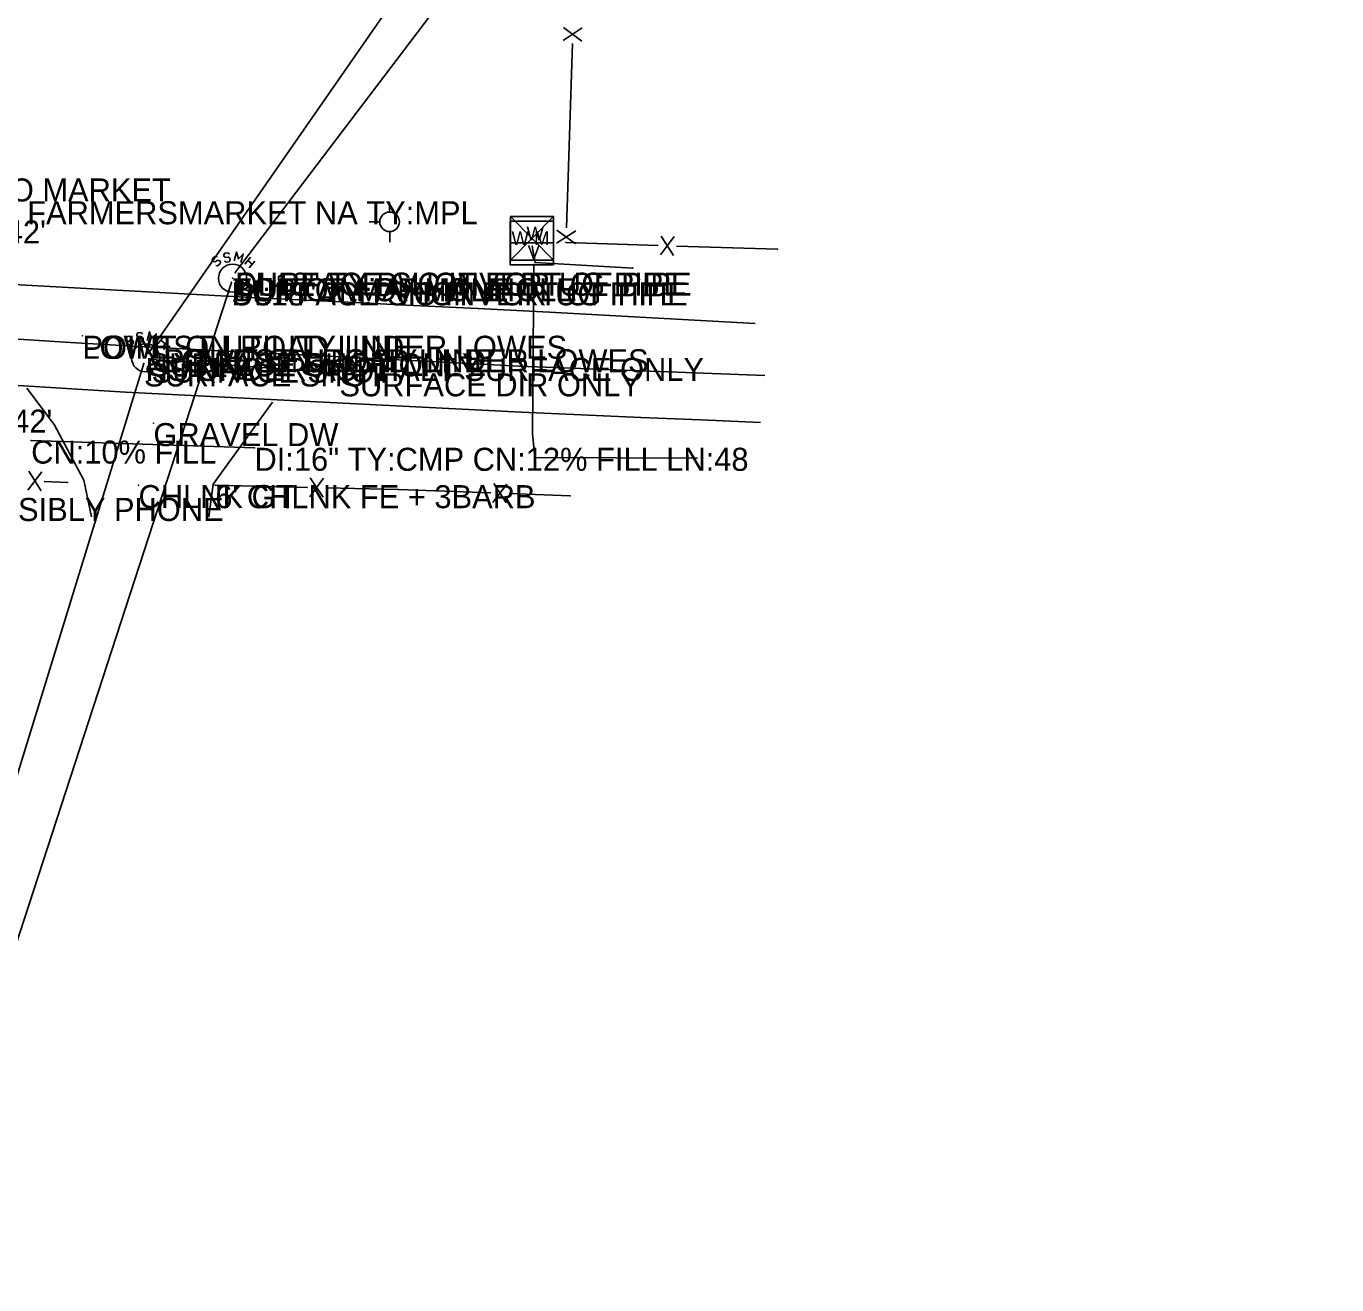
# Model space of a CAD drawing. Extents: x 929765 to 934279, y 1533086 to 1541189.
# Drawn here: x 932210.9 to 932495.1, y 1537318.7 to 1537591.7 of the extents above; entities that cross this region are included whole.
import ezdxf

# ---------------------------------------------------------------- set-up
doc = ezdxf.new("R2010")
doc.units = 0
for name, color, linetype in [('S_CROSS_DRAIN', 7, 'Continuous'), ('S_CROSS_DRAIN_ANNOT', 7, 'Continuous'), ('S_DRG_PT_SYM', 7, 'Continuous'), ('S_DRIVEWAY', 7, 'Continuous'), ('S_EDGE_PAVEMENT', 7, 'Continuous'), ('S_ELECTRIC_UTILITIES_ANNOT', 7, 'Continuous'), ('S_FENCE', 7, 'Continuous'), ('S_FENCE_ANNOT', 7, 'Continuous'), ('S_MANHOLE_ANNOT', 7, 'Continuous'), ('S_MSC_PT_SYM', 7, 'Continuous'), ('S_PAVEMENT_CROWN', 7, 'Continuous'), ('S_SANITARY_SEWER', 7, 'Continuous'), ('S_SANITARY_SEWER_ANNOT', 7, 'Continuous'), ('S_SIGN_ANNOT', 7, 'Continuous'), ('S_SURVEY_TEXT_ANNOT', 7, 'Continuous'), ('S_UNDERGROUND_CABLE_ANNOT', 7, 'Continuous'), ('S_UTILITY_POLE', 7, 'Continuous'), ('S_UTL_PT_SYM', 7, 'Continuous'), ('S_WATER_UTILITIES', 7, 'Continuous')]:
    doc.layers.add(name, color=color, linetype=linetype)

msp = doc.modelspace()

# ---------------------------------------------------------------- linework, layer by layer
at = {"layer": 'S_CROSS_DRAIN'}
msp.add_line((932260.38, 1537500.24), (932211.95, 1537501.81), dxfattribs=at)
at = {"layer": 'S_DRG_PT_SYM'}
for points in [[(932211.95, 1537501.81), (932211.95, 1537501.86), (932211.95, 1537501.81), (932211.9, 1537501.81), (932211.95, 1537501.81), (932211.95, 1537501.76), (932211.95, 1537501.81), (932212, 1537501.81)], [(932260.38, 1537500.24), (932260.38, 1537500.29), (932260.38, 1537500.24), (932260.33, 1537500.24), (932260.38, 1537500.24), (932260.38, 1537500.19), (932260.38, 1537500.24), (932260.43, 1537500.24)]]:
    msp.add_lwpolyline(points, dxfattribs=at)
at = {"layer": 'S_DRIVEWAY'}
for points in [[(932225.03, 1537485.24), (932223.34, 1537493.18), (932216.93, 1537505.32), (932210.97, 1537513.16)], [(932264.28, 1537510.16), (932251.42, 1537492.35), (932250.46, 1537485.26)]]:
    msp.add_lwpolyline(points, dxfattribs=at)
at = {"layer": 'S_EDGE_PAVEMENT'}
for points in [[(932368.97, 1537527.2), (932346.67, 1537528.43), (932324.37, 1537529.66), (932308.86, 1537530.43), (932293.35, 1537531.2), (932277.84, 1537531.96), (932262.32, 1537532.73), (932247.78, 1537533.51), (932233.23, 1537534.29), (932218.68, 1537535.07), (932204.14, 1537535.85), (932182.78, 1537536.97)], [(932061.04, 1537519.67), (932075.98, 1537519.33), (932090.91, 1537518.99), (932105.85, 1537518.66), (932120.78, 1537518.32), (932134.72, 1537517.68), (932148.65, 1537517.03), (932162.59, 1537516.39), (932176.52, 1537515.74), (932190.49, 1537514.88), (932204.46, 1537514.03), (932218.44, 1537513.17), (932232.41, 1537512.32), (932253.88, 1537511.23), (932275.34, 1537510.15), (932296.81, 1537509.07), (932318.28, 1537507.98), (932331.24, 1537507.41), (932344.21, 1537506.84), (932357.18, 1537506.27), (932370.14, 1537505.7)]]:
    msp.add_lwpolyline(points, dxfattribs=at)
at = {"layer": 'S_FENCE'}
for p, q in [((932331.49, 1537591.32), (932327.3, 1537588.58)), ((932331.49, 1537591.32), (932327.3, 1537588.58)), ((932327.4, 1537591.45), (932331.4, 1537588.45)), ((932327.4, 1537591.45), (932331.4, 1537588.45)), ((932330.08, 1537547.34), (932325.9, 1537544.61)), ((932330.08, 1537547.34), (932325.9, 1537544.61)), ((932325.99, 1537547.47), (932329.99, 1537544.48)), ((932325.99, 1537547.47), (932329.99, 1537544.48)), ((932348.43, 1537542.07), (932351.42, 1537546.08)), ((932348.43, 1537542.07), (932351.42, 1537546.08)), ((932348.56, 1537546.17), (932351.29, 1537541.98)), ((932348.56, 1537546.17), (932351.29, 1537541.98)), ((932211.24, 1537491.04), (932214.29, 1537495)), ((932211.24, 1537491.04), (932214.29, 1537495)), ((932211.43, 1537495.13), (932214.1, 1537490.91)), ((932211.43, 1537495.13), (932214.1, 1537490.91)), ((932272.38, 1537489.59), (932275.35, 1537493.62)), ((932272.38, 1537489.59), (932275.35, 1537493.62)), ((932272.48, 1537493.69), (932275.25, 1537489.52)), ((932272.48, 1537493.69), (932275.25, 1537489.52)), ((932312.11, 1537488.37), (932315.13, 1537492.36)), ((932312.11, 1537488.37), (932315.13, 1537492.36)), ((932312.26, 1537492.46), (932314.97, 1537488.26)), ((932312.26, 1537492.46), (932314.97, 1537488.26))]:
    msp.add_line(p, q, dxfattribs=at)
for points in [[(932329.33, 1537587.95), (932328.05, 1537547.97)], [(932329.33, 1537587.95), (932328.05, 1537547.97)], [(932327.95, 1537544.78), (932347.93, 1537544.14)], [(932327.95, 1537544.78), (932347.93, 1537544.14)], [(932351.92, 1537544.01), (932373.82, 1537543.31)], [(932351.92, 1537544.01), (932373.82, 1537543.31)], [(932214.76, 1537492.93), (932219.83, 1537492.69)], [(932214.76, 1537492.93), (932219.83, 1537492.69)], [(932251.87, 1537492.13), (932271.86, 1537491.65)], [(932251.87, 1537492.13), (932271.86, 1537491.65)], [(932275.86, 1537491.56), (932291.63, 1537491.18)], [(932275.86, 1537491.56), (932291.63, 1537491.18)], [(932291.63, 1537491.18), (932311.62, 1537490.44)], [(932291.63, 1537491.18), (932311.62, 1537490.44)], [(932315.61, 1537490.29), (932328.84, 1537489.8)], [(932315.61, 1537490.29), (932328.84, 1537489.8)]]:
    msp.add_lwpolyline(points, dxfattribs=at)
at = {"layer": 'S_MSC_PT_SYM'}
for points in [[(932327.95, 1537544.78), (932327.95, 1537544.83), (932327.95, 1537544.78), (932327.9, 1537544.78), (932327.95, 1537544.78), (932327.95, 1537544.73), (932327.95, 1537544.78), (932328, 1537544.78)], [(932373.82, 1537543.31), (932373.82, 1537543.36), (932373.82, 1537543.31), (932373.77, 1537543.31), (932373.82, 1537543.31), (932373.82, 1537543.26), (932373.82, 1537543.31), (932373.87, 1537543.31)], [(932256.2, 1537538.23), (932256.2, 1537538.28), (932256.2, 1537538.23), (932256.15, 1537538.23), (932256.2, 1537538.23), (932256.2, 1537538.18), (932256.2, 1537538.23), (932256.25, 1537538.23)], [(932255.38, 1537536.13), (932255.38, 1537536.18), (932255.38, 1537536.13), (932255.33, 1537536.13), (932255.38, 1537536.13), (932255.38, 1537536.08), (932255.38, 1537536.13), (932255.43, 1537536.13)], [(932223.06, 1537524.54), (932223.06, 1537524.59), (932223.06, 1537524.54), (932223.01, 1537524.54), (932223.06, 1537524.54), (932223.06, 1537524.49), (932223.06, 1537524.54), (932223.11, 1537524.54)], [(932240.74, 1537521.62), (932240.74, 1537521.67), (932240.74, 1537521.62), (932240.69, 1537521.62), (932240.74, 1537521.62), (932240.74, 1537521.57), (932240.74, 1537521.62), (932240.79, 1537521.62)], [(932238.46, 1537505.59), (932238.46, 1537505.65), (932238.46, 1537505.59), (932238.41, 1537505.59), (932238.46, 1537505.59), (932238.46, 1537505.54), (932238.46, 1537505.59), (932238.51, 1537505.59)], [(932219.83, 1537492.69), (932219.83, 1537492.74), (932219.83, 1537492.69), (932219.78, 1537492.69), (932219.83, 1537492.69), (932219.83, 1537492.64), (932219.83, 1537492.69), (932219.88, 1537492.69)], [(932235.23, 1537492.15), (932235.23, 1537492.2), (932235.23, 1537492.15), (932235.18, 1537492.15), (932235.23, 1537492.15), (932235.23, 1537492.1), (932235.23, 1537492.15), (932235.28, 1537492.15)], [(932251.87, 1537492.13), (932251.87, 1537492.18), (932251.87, 1537492.13), (932251.82, 1537492.13), (932251.87, 1537492.13), (932251.87, 1537492.08), (932251.87, 1537492.13), (932251.92, 1537492.13)], [(932291.63, 1537491.18), (932291.63, 1537491.23), (932291.63, 1537491.18), (932291.58, 1537491.18), (932291.63, 1537491.18), (932291.63, 1537491.13), (932291.63, 1537491.18), (932291.68, 1537491.18)], [(932328.84, 1537489.8), (932328.84, 1537489.85), (932328.84, 1537489.8), (932328.79, 1537489.8), (932328.84, 1537489.8), (932328.84, 1537489.75), (932328.84, 1537489.8), (932328.89, 1537489.8)]]:
    msp.add_lwpolyline(points, dxfattribs=at)
at = {"layer": 'S_PAVEMENT_CROWN'}
msp.add_lwpolyline([(932063.43, 1537531.97), (932077.89, 1537531.23), (932092.36, 1537530.49), (932106.82, 1537529.75), (932121.29, 1537529.01), (932135.07, 1537528.19), (932148.84, 1537527.38), (932162.62, 1537526.56), (932176.4, 1537525.75), (932191.1, 1537524.87), (932205.8, 1537523.99), (932220.5, 1537523.11), (932235.2, 1537522.24), (932255.86, 1537521.16), (932276.51, 1537520.09), (932297.17, 1537519.01), (932317.82, 1537517.94), (932331.13, 1537517.43), (932344.43, 1537516.92), (932357.74, 1537516.42), (932371.04, 1537515.91)], dxfattribs=at)
at = {"layer": 'S_SANITARY_SEWER'}
for p, q in [((932495.13, 1537853.38), (932256.2, 1537538.23)), ((932461.19, 1537843), (932237.41, 1537520.73)), ((932251.3, 1537541.33), (932251.22, 1537540.94)), ((932251.22, 1537540.94), (932251.42, 1537540.67)), ((932251.84, 1537541.72), (932251.3, 1537541.33)), ((932251.42, 1537540.67), (932251.84, 1537540.56)), ((932252.27, 1537541.64), (932251.84, 1537541.72)), ((932251.84, 1537540.56), (932252.39, 1537540.91)), ((932252.39, 1537539.74), (932252, 1537539.82)), ((932252.39, 1537540.91), (932252.85, 1537540.83)), ((932252.93, 1537540.13), (932252.39, 1537539.74)), ((932252.85, 1537540.83), (932253.01, 1537540.56)), ((932253.01, 1537540.56), (932252.93, 1537540.13)), ((932258.28, 1537540.09), (932259.52, 1537541.56)), ((932258.94, 1537540.87), (932259.9, 1537540.05)), ((932260.49, 1537540.75), (932259.25, 1537539.28)), ((932255.38, 1537536.13), (932170.26, 1537274.65)), ((932232.44, 1537524.05), (932232.36, 1537523.66)), ((932232.36, 1537523.66), (932232.55, 1537523.39)), ((932232.98, 1537524.44), (932232.44, 1537524.05)), ((932232.55, 1537523.39), (932232.98, 1537523.27)), ((932233.41, 1537524.36), (932232.98, 1537524.44)), ((932232.98, 1537523.27), (932233.52, 1537523.62)), ((932233.52, 1537522.46), (932233.14, 1537522.54)), ((932233.52, 1537523.62), (932233.99, 1537523.54)), ((932234.07, 1537522.85), (932233.52, 1537522.46)), ((932233.99, 1537523.54), (932234.14, 1537523.27)), ((932234.14, 1537523.27), (932234.07, 1537522.85)), ((932239.41, 1537522.81), (932240.65, 1537524.28)), ((932240.07, 1537523.58), (932241.04, 1537522.77)), ((932241.62, 1537523.47), (932240.38, 1537521.99)), ((932236.41, 1537518.54), (932154.58, 1537252.96)), ((932238.06, 1537519.37), (932278.81, 1537516.4))]:
    msp.add_line(p, q, dxfattribs=at)
for points in [[(932254.94, 1537542.26), (932254.6, 1537542.53), (932253.94, 1537542.46), (932253.7, 1537542.11), (932253.74, 1537541.8), (932254.09, 1537541.49), (932254.71, 1537541.6), (932255.1, 1537541.29), (932255.14, 1537540.98), (932254.87, 1537540.6), (932254.25, 1537540.52), (932253.9, 1537540.79)], [(932257.39, 1537540.4), (932257.93, 1537542.26), (932256.88, 1537541.25), (932256.49, 1537542.69), (932255.95, 1537540.83)], [(932238.52, 1537523.12), (932239.06, 1537524.98), (932238.02, 1537523.97), (932237.63, 1537525.4), (932237.09, 1537523.54)], [(932236.08, 1537524.98), (932235.73, 1537525.25), (932235.07, 1537525.17), (932234.84, 1537524.82), (932234.88, 1537524.51), (932235.23, 1537524.2), (932235.85, 1537524.32), (932236.24, 1537524.01), (932236.27, 1537523.7), (932236, 1537523.31), (932235.38, 1537523.23), (932235.03, 1537523.51)]]:
    msp.add_lwpolyline(points, dxfattribs=at)
for centre in [(932255.63, 1537537.03), (932236.77, 1537519.75)]:
    msp.add_circle(centre, 3.05, dxfattribs=at)
at = {"layer": 'S_UTILITY_POLE'}
for p, q in [((932289.69, 1537551.37), (932289.69, 1537553.62)), ((932287.6, 1537549.24), (932285.27, 1537549.24)), ((932289.77, 1537544.82), (932289.77, 1537547.14))]:
    msp.add_line(p, q, dxfattribs=at)
msp.add_circle((932289.69, 1537549.26), 2.13, dxfattribs=at)
at = {"layer": 'S_UTL_PT_SYM'}
for points in [[(932320.61, 1537543.96), (932320.61, 1537544.01), (932320.61, 1537543.96), (932320.56, 1537543.96), (932320.61, 1537543.96), (932320.61, 1537543.91), (932320.61, 1537543.96), (932320.66, 1537543.96)], [(932320.98, 1537539.97), (932320.98, 1537540.02), (932320.98, 1537539.97), (932320.93, 1537539.97), (932320.98, 1537539.97), (932320.98, 1537539.92), (932320.98, 1537539.97), (932321.03, 1537539.97)], [(932321.25, 1537540.47), (932321.25, 1537540.52), (932321.25, 1537540.47), (932321.2, 1537540.47), (932321.25, 1537540.47), (932321.25, 1537540.42), (932321.25, 1537540.47), (932321.3, 1537540.47)], [(932255.63, 1537537.03), (932255.63, 1537537.08), (932255.63, 1537537.03), (932255.58, 1537537.03), (932255.63, 1537537.03), (932255.63, 1537536.98), (932255.63, 1537537.03), (932255.68, 1537537.03)], [(932256.2, 1537538.23), (932256.2, 1537538.28), (932256.2, 1537538.23), (932256.15, 1537538.23), (932256.2, 1537538.23), (932256.2, 1537538.18), (932256.2, 1537538.23), (932256.25, 1537538.23)], [(932342.41, 1537539.23), (932342.41, 1537539.28), (932342.41, 1537539.23), (932342.36, 1537539.23), (932342.41, 1537539.23), (932342.41, 1537539.18), (932342.41, 1537539.23), (932342.46, 1537539.23)], [(932255.38, 1537536.13), (932255.38, 1537536.18), (932255.38, 1537536.13), (932255.33, 1537536.13), (932255.38, 1537536.13), (932255.38, 1537536.08), (932255.38, 1537536.13), (932255.43, 1537536.13)], [(932223.06, 1537524.54), (932223.06, 1537524.59), (932223.06, 1537524.54), (932223.01, 1537524.54), (932223.06, 1537524.54), (932223.06, 1537524.49), (932223.06, 1537524.54), (932223.11, 1537524.54)], [(932237.41, 1537520.73), (932237.41, 1537520.78), (932237.41, 1537520.73), (932237.36, 1537520.73), (932237.41, 1537520.73), (932237.41, 1537520.68), (932237.41, 1537520.73), (932237.46, 1537520.73)], [(932240.74, 1537521.62), (932240.74, 1537521.67), (932240.74, 1537521.62), (932240.69, 1537521.62), (932240.74, 1537521.62), (932240.74, 1537521.57), (932240.74, 1537521.62), (932240.79, 1537521.62)], [(932236.41, 1537518.54), (932236.41, 1537518.59), (932236.41, 1537518.54), (932236.36, 1537518.54), (932236.41, 1537518.54), (932236.41, 1537518.49), (932236.41, 1537518.54), (932236.46, 1537518.54)], [(932238.06, 1537519.37), (932238.06, 1537519.42), (932238.06, 1537519.37), (932238.01, 1537519.37), (932238.06, 1537519.37), (932238.06, 1537519.32), (932238.06, 1537519.37), (932238.11, 1537519.37)], [(932278.81, 1537516.4), (932278.81, 1537516.45), (932278.81, 1537516.4), (932278.76, 1537516.4), (932278.81, 1537516.4), (932278.81, 1537516.35), (932278.81, 1537516.4), (932278.86, 1537516.4)], [(932320.67, 1537503.27), (932320.67, 1537503.32), (932320.67, 1537503.27), (932320.62, 1537503.27), (932320.67, 1537503.27), (932320.67, 1537503.22), (932320.67, 1537503.27), (932320.72, 1537503.27)], [(932321.22, 1537498.14), (932321.22, 1537498.19), (932321.22, 1537498.14), (932321.17, 1537498.14), (932321.22, 1537498.14), (932321.22, 1537498.09), (932321.22, 1537498.14), (932321.27, 1537498.14)], [(932356.33, 1537497.98), (932356.33, 1537498.03), (932356.33, 1537497.98), (932356.28, 1537497.98), (932356.33, 1537497.98), (932356.33, 1537497.93), (932356.33, 1537497.98), (932356.38, 1537497.98)]]:
    msp.add_lwpolyline(points, dxfattribs=at)
at = {"layer": 'S_WATER_UTILITIES'}
for p, q in [((932315.83, 1537549.37), (932325.25, 1537549.37)), ((932315.83, 1537539.96), (932315.83, 1537549.37)), ((932315.92, 1537550.45), (932325.26, 1537550.45)), ((932315.92, 1537550.45), (932315.92, 1537540.95)), ((932315.92, 1537550.45), (932325.26, 1537540.95)), ((932325.26, 1537550.45), (932315.92, 1537540.95)), ((932325.25, 1537549.37), (932325.25, 1537539.96)), ((932325.26, 1537550.45), (932325.26, 1537540.95)), ((932315.83, 1537544.68), (932325.25, 1537544.68)), ((932320.61, 1537543.96), (932321.25, 1537540.47)), ((932325.25, 1537539.96), (932315.83, 1537539.96)), ((932315.92, 1537540.95), (932325.26, 1537540.95)), ((932320.98, 1537539.97), (932320.67, 1537503.27)), ((932321.25, 1537540.47), (932342.41, 1537539.23)), ((932320.67, 1537503.27), (932321.22, 1537498.14)), ((932321.22, 1537498.14), (932356.33, 1537497.98))]:
    msp.add_line(p, q, dxfattribs=at)

# ---------------------------------------------------------------- texts
at = {"layer": 'S_CROSS_DRAIN_ANNOT'}
for s, p in [('DI:72" TY:CMP CN:0% FILL LN:42\'', (932110.43, 1537544.57)), ('DI:72" TY:CMP CN:0% FILL LN:42\'', (932111.82, 1537503.52)), ('CN:10% FILL', (932211.95, 1537496.81)), ('DI:16" TY:CMP CN:12% FILL LN:48', (932260.38, 1537495.24))]:
    msp.add_text(s, height=5, dxfattribs=at).set_placement(p)
at = {"layer": 'S_ELECTRIC_UTILITIES_ANNOT'}
for p in [(932223.06, 1537519.54), (932240.74, 1537516.62)]:
    msp.add_text('LOWEST UTILITY LINE', height=5, dxfattribs=at).set_placement(p)
at = {"layer": 'S_FENCE_ANNOT'}
msp.add_text("6' CHLNK FE + 3BARB", height=5, dxfattribs=at).set_placement((932251.87, 1537487.13))
at = {"layer": 'S_MANHOLE_ANNOT'}
msp.add_text('BOTTOM OF MANHOLE', height=5, dxfattribs=at).set_placement((932255.63, 1537532.03))
at = {"layer": 'S_SANITARY_SEWER_ANNOT'}
for s, p in [('TOP OF MANHOLE', (932255.63, 1537532.03)), ('DI:18" TY:PVC INVERT OF PIPE', (932256.2, 1537533.23)), ('DI:18" TY:PVC INVERT OF PIPE', (932255.38, 1537531.13)), ('HS UNDER ASPHALT SURFACE ONLY', (932236.77, 1537514.75)), ('SURFACE SHOT ONLY', (932237.41, 1537515.73)), ('SURFACE SHOT', (932236.41, 1537513.54)), ('SURFACE SHOT', (932238.06, 1537514.37)), ('SURFACE DIR ONLY', (932278.81, 1537511.4))]:
    msp.add_text(s, height=5, dxfattribs=at).set_placement(p)
at = {"layer": 'S_SIGN_ANNOT'}
msp.add_text('4.50 FARMERSMARKET NA TY:MPL', height=5, dxfattribs=at).set_placement((932196.22, 1537548.73))
at = {"layer": 'S_SURVEY_TEXT_ANNOT'}
for s, p in [('ASPHALT DW TO MARKET', (932157.91, 1537553.67)), ('SURFACE SHOT FOR UG PIPE', (932256.2, 1537533.23)), ('SURFACE SHOT FOR UG PIPE', (932255.38, 1537531.13)), ('POINT ON ROAD UNDER LOWES', (932223.06, 1537519.54)), ('POINT ON ROAD UNDER LOWES', (932240.74, 1537516.62)), ('GRAVEL DW', (932238.46, 1537500.59)), ('CHLNK GT', (932235.23, 1537487.15))]:
    msp.add_text(s, height=5, dxfattribs=at).set_placement(p)
at = {"layer": 'S_UNDERGROUND_CABLE_ANNOT'}
msp.add_text('CTY OF MAGNOLIA POSIBLY PHONE', height=5, dxfattribs=at).set_placement((932135.91, 1537484.36))
at = {"layer": 'S_WATER_UTILITIES'}
for s, p in [('W', (932319.38, 1537545.21)), ('W M', (932316.12, 1537544.21)), ('V', (932319.62, 1537541.15))]:
    msp.add_text(s, height=3, rotation=360, dxfattribs=at).set_placement(p)

doc.saveas('drawing.dxf')
